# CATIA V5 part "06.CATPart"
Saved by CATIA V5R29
Part number: 06
Bounding box of the stored display mesh (mm): x -2.499 to 2.499, y 0 to 65, z -2.472 to 2.472
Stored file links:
  C:\Users\FERIDUN\Desktop\montaj3\06.CATPart
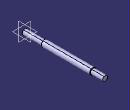
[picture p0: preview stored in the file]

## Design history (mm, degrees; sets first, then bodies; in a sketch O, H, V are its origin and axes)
Body1 (main body)
  Sketch1 on yz-plane, origin (0, 0, 0), H (0, 1, 0), V (0, 0, 1)
    line L1 (0, 0) -> (0, 2)
    line L2 (0, 2) -> (16, 2)
    line L3 (16, 2) -> (16, 2.5)
    line L4 (16, 2.5) -> (55, 2.5)
    line L5 (55, 2.5) -> (55, 2)
    point P5 (55, 2)
    line L6 (55, 2) -> (65, 2)
    line L7 (65, 2) -> (65, 0)
    point P7 (65, 0)
    axis line L8 (0, 0) -> (129.3949, 0)
    length L2 = 16
    length L4 = 39
    length L6 = 10
    radius about axis L2 L8 = 2
    radius about axis L4 L8 = 2.5
    vertical: L1 V, L3 V, L5 V, L7 V
    horizontal: L2 H, L4 H, L6 H, L8 H
    coincidence: P5 L2, P7 H
  Shaft1: profile Sketch1, axis Sketch1.L8, angle 360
